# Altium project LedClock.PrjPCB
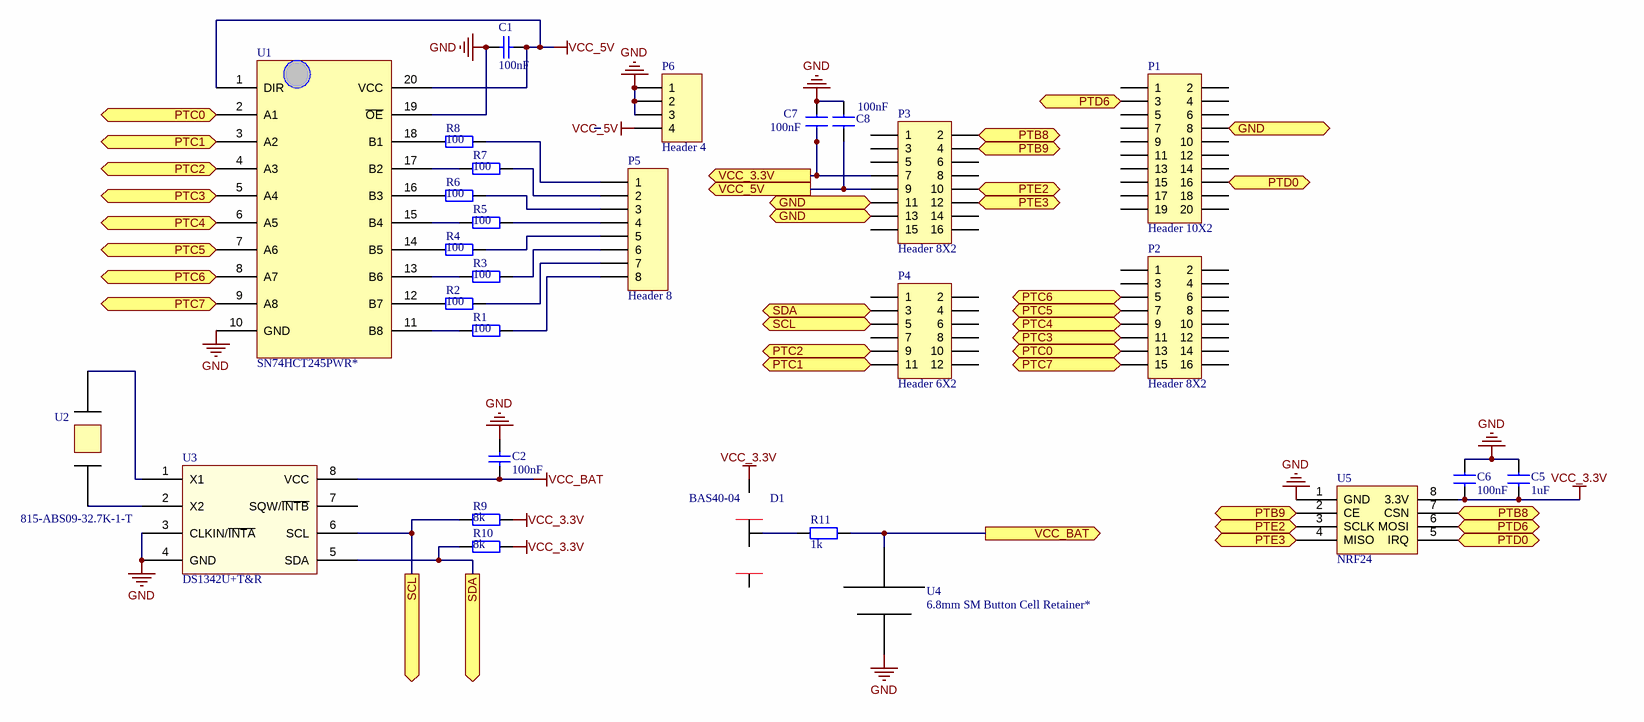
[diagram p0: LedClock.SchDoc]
1 sheet, 29 parts. Net scope: flat (ports and power ports of the same name join across sheets).
Board file: LedClock.PcbDoc

## Sheet LedClock.SchDoc
size A3; Organization: HSLU T&A; Address1: Abteilung Elektrotechnik; Address2: Technikumsstrasse 21; Address3: CH-6048 Horw

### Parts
C1  100nF  [0805]
C2  100nF  [0805]
C5  1uF  [0805]
C6  100nF  [0805]
C7  100nF  [0805]
C8  100nF  [0805]
D1  BAS40-04  [SOT23]
P1  Header 10X2  [HDR2X10]
P2  Header 8X2  [HDR2X8]
P3  Header 8X2  [HDR2X8]
P4  Header 6X2  [HDR2X6]
P5  Header 8  [HDR1X8]
P6  Header 4  [HDR1X4]
R1  100  [0805]
R2  100  [0805]
R3  100  [0805]
R4  100  [0805]
R5  100  [0805]
R6  100  [0805]
R7  100  [0805]
R8  100  [0805]
R9  8k  [0805]
R10  8k  [0805]
R11  1k  [0805]
U1  SN74HCT245PWR*  [SN74HCT245PWR_20P]
U2  815-ABS09-32.7K-1-T  [815-ABS09-32.7K-1-T]
U3  DS1342U+T&R  [uSOP-8]
U4  6.8mm SM Button Cell Retainer*  [6.8mm SM Button Cell Retainer]
U5  NRF24  [HEADER2X4]

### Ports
GND (out), PTB8 (in), PTB8 (out), PTB9 (in), PTB9 (out), PTC0 (in), PTC0 (out), PTC1 (in), PTC1 (out), PTC2 (in), PTC2 (out), PTC3 (in), PTC3 (out), PTC4 (in), PTC4 (out), PTC5 (in), PTC5 (out), PTC6 (in), PTC6 (out), PTC7 (in), PTC7 (out), PTD0 (in), PTD0 (out), PTD6 (in), PTD6 (out), PTE2 (in), PTE2 (out), PTE3 (in), PTE3 (out), SCL (in), SCL (out), SDA (in), SDA (out), VCC_3.3V (out), VCC_5V (out), VCC_BAT (out)

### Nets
GND: C1.2 C2.2 C5.1 C6.1 C7.1 C8.1 P6.1 P6.2 P6.3 U1.10(GND) U1.19(~{OE}) U3.3(CLKIN/~{INTA}) U3.4(GND) U4.2 U5.1(GND)
VCC_3.3V: C5.2 C6.2 D1.1 R9.2 R10.2 U5.8(3.3V)
VCC_5V: C1.1 P6.4 U1.1(DIR) U1.20(VCC)
VCC_BAT: C2.1 U3.8(VCC)
NetC7_2: C7.2 P3.7 ; port VCC_3.3V
NetC8_2: C8.2 P3.9 ; port VCC_5V
NetD1_3: D1.3 R11.1
NetP1_3: P1.3 U5.6(MOSI) ; port PTD6
NetP1_8: P1.8 P3.11 P3.13 ; port GND
NetP1_16: P1.16 U5.5(IRQ) ; port PTD0
NetP2_5: P2.5 U1.8(A7) ; port PTC6
NetP2_7: P2.7 U1.7(A6) ; port PTC5
NetP2_9: P2.9 U1.6(A5) ; port PTC4
NetP2_11: P2.11 U1.5(A4) ; port PTC3
NetP2_13: P2.13 U1.2(A1) ; port PTC0
NetP2_15: P2.15 U1.9(A8) ; port PTC7
NetP3_2: P3.2 U5.7(CSN) ; port PTB8
NetP3_4: P3.4 U5.2(CE) ; port PTB9
NetP3_10: P3.10 U5.3(SCLK) ; port PTE2
NetP3_12: P3.12 U5.4(MISO) ; port PTE3
NetP4_3: P4.3 R10.1 U3.5(SDA) ; port SDA
NetP4_5: P4.5 R9.1 U3.6(SCL) ; port SCL
NetP4_9: P4.9 U1.4(A3) ; port PTC2
NetP4_11: P4.11 U1.3(A2) ; port PTC1
NetP5_1: P5.1 R8.2
NetP5_2: P5.2 R7.2
NetP5_3: P5.3 R6.2
NetP5_4: P5.4 R5.2
NetP5_5: P5.5 R4.2
NetP5_6: P5.6 R3.2
NetP5_7: P5.7 R2.2
NetP5_8: P5.8 R1.2
NetR1_1: R1.1 U1.11(B8)
NetR2_1: R2.1 U1.12(B7)
NetR3_1: R3.1 U1.13(B6)
NetR4_1: R4.1 U1.14(B5)
NetR5_1: R5.1 U1.15(B4)
NetR6_1: R6.1 U1.16(B3)
NetR7_1: R7.1 U1.17(B2)
NetR8_1: R8.1 U1.18(B1)
NetR11_2: R11.2 U4.1 ; port VCC_BAT
NetU2_1: U2.1 U3.2(X2)
NetU2_2: U2.2 U3.1(X1)

Not connected (* = marked no-connect by the designer): D1 2; P1 1 2 4 5 6 7 9 10 11 12 13 14 15 17 18 19 20; P2 1 2 3 4 6 8 10 12 14 16; P3 1 3 5 6 8 14 15 16; P4 1 2 4 6 7 8 10 12; U3 7(SQW/~{INTB})

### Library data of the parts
C1 C2 = CapNP: Chip Capacitor SMD 0805
C5-C8 = C?: Normaler Kondensator
P1 = Header 10X2: Header, 10-Pin, Dual row
P2 P3 = Header 8X2: Header, 8-Pin, Dual row
P4 = Header 6X2: Header, 6-Pin, Dual row
P5 = Header 8: Header, 8-Pin
P6 = Header 4: Header, 4-Pin
R1-R11 = Res: Chip Resistor SMD 0805
U1 = SN74HCT245PWR_20P
U4 = 6.8mm SM Button Cell Retainer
